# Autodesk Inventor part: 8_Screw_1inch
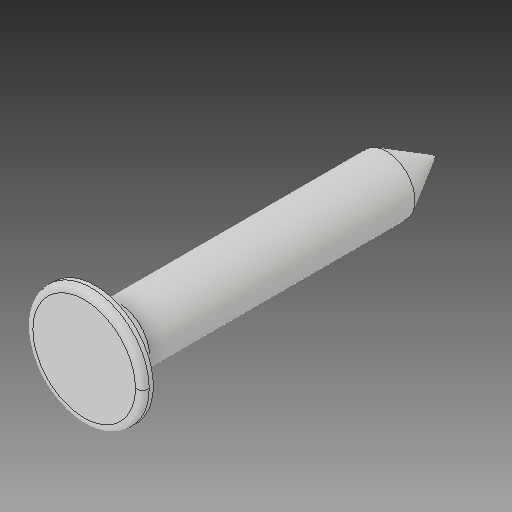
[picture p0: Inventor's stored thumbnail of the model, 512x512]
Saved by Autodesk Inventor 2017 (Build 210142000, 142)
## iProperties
Created: 2017-05
Part Number: 8_Screw_1inch
Material: Generic
Document SubType Name: Modeling
Designer: Savy
Density: 1 g/cm^3
Appearance: Default
Mass: 0.383039 g
Surface Area: 4.0928 cm^2
Volume: 0.383039 cm^3
Author: Savy
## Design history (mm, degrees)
feature "SOLID1"
body "Solid1"
